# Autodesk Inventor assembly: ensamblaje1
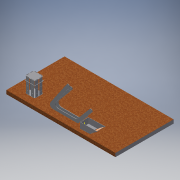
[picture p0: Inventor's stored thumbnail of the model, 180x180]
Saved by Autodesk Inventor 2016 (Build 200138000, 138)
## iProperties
Created: 2016-06
Part Number: ensamblaje1
Material: Genérico
Document SubType Name: Assembly
Designer: adm
Author: adm
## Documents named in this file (7)
- C:\Users\adm\Desktop\el ultimo\ensamblaje1.iam
- C:\Users\adm\Desktop\el ultimo\tablero.ipt
- C:\Users\adm\Desktop\SOPORTE INCLINADO.ipt
- C:\Users\adm\Desktop\SOPORTE1.ipt
- C:\Users\adm\Desktop\recepcion 2\Ensamblaje2.iam
- C:\Users\adm\Desktop\SOPORTE INCLINADO (motor).ipt
- C:\Users\adm\Desktop\Soportes\Ensamblaje1.iam
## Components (7 placed, 6 different names)
1. tablero:1 — Coincidencia:1, Coincidencia:4, Coincidencia:10, Coincidencia:13
2. SOPORTE INCLINADO:1 — Coincidencia:1, Coincidencia:2, Coincidencia:3, Coincidencia:9, Nivelación:1
3. SOPORTE1:1 — Coincidencia:2, Coincidencia:3, Coincidencia:9
4. Ensamblaje2:1 [sub-assembly] — Coincidencia:4
5. SOPORTE1:2 — Coincidencia:11, Coincidencia:12
6. SOPORTE INCLINADO (motor):1 — Coincidencia:10, Nivelación:1, Coincidencia:11, Coincidencia:12
7. Ensamblaje1:1 [sub-assembly] — Coincidencia:13
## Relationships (10: Mate 9, Flush 1)
- Coincidencia:1 [Mate]: tablero:1 ↔ SOPORTE INCLINADO:1
- Coincidencia:2 [Mate]: SOPORTE INCLINADO:1 ↔ SOPORTE1:1
- Coincidencia:3 [Mate]: SOPORTE INCLINADO:1 ↔ SOPORTE1:1
- Coincidencia:4 [Mate]: tablero:1 ↔ Ensamblaje2:1
- Coincidencia:9 [Mate]: SOPORTE INCLINADO:1 ↔ SOPORTE1:1
- Coincidencia:10 [Mate]: tablero:1 ↔ SOPORTE INCLINADO (motor):1
- Nivelación:1 [Flush]: SOPORTE INCLINADO:1 ↔ SOPORTE INCLINADO (motor):1
- Coincidencia:11 [Mate]: SOPORTE1:2 ↔ SOPORTE INCLINADO (motor):1
- Coincidencia:12 [Mate]: SOPORTE1:2 ↔ SOPORTE INCLINADO (motor):1
- Coincidencia:13 [Mate]: tablero:1 ↔ Ensamblaje1:1
